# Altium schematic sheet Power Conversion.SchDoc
size A4
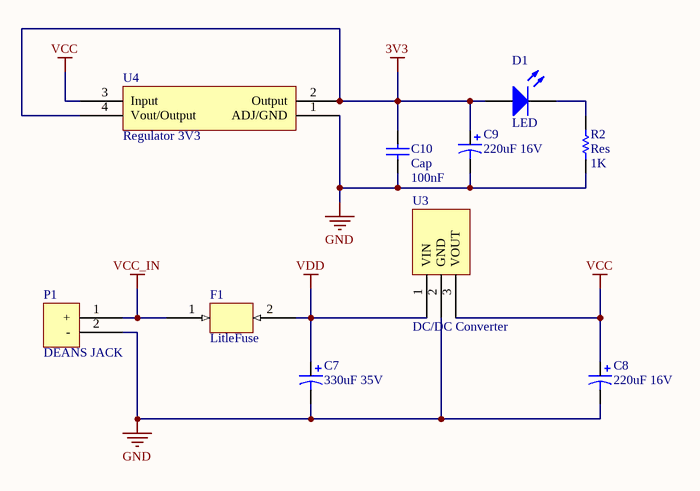
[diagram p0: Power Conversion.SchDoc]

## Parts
C7  330uF 35V  [CAP 330uF 35V SMD]
C8  220uF 16V  [CAP 220uF 16V]
C9  220uF 16V  [CAP 220uF 16V]
C10  Cap  value 100nF  [0603-CAP]
D1  LED  [CHIPLED_0603]
F1  LitleFuse  [LitleFuse]
P1  DEANS JACK  [Deans Jack]
R2  Res  value 1K  [0603-RES]
U3  DC/DC Converter  [DC/DC Converter]
U4  Regulator 3V3  [Regulator 3V3 SOT230]

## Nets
3V3: C9.1 C10.1 D1.1(A) U4.2(Output) U4.4(Vout/Output)
GND: C7.2 C8.2 C9.2 C10.2 P1.2(-) R2.1 U3.2(GND) U4.1(ADJ/GND)
VCC: C8.1 U3.3(VOUT) U4.3(Input)
VCC_IN: F1.1 P1.1(+)
VDD: C7.1 F1.2 U3.1(VIN)
NetD1_2: D1.2(K) R2.2

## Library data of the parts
C10 = Cap: Capacitor
D1 = LED: Typical INFRARED GaAs LED
R2 = Res: Resistor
